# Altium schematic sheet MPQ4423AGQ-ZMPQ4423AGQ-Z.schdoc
size 127 x 101 mm
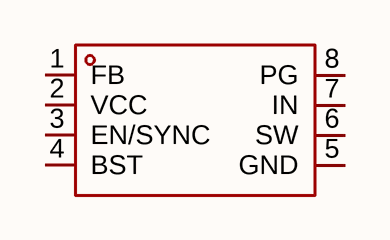
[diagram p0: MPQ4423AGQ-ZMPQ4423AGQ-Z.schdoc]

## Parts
U?  mpq4423agq-z  [QFN-8_L3.0-W3.0-P0.65-TL-MPQ4423HGQ-Z]  (value not drawn)

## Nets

Not connected (* = marked no-connect by the designer): U? 1(FB) 2(VCC) 3(EN/SYNC) 4(BST) 5(GND) 6(SW) 7(IN) 8(PG)

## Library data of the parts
U? = mpq4423agq-z: 功能类型:降压型;工作电压:4V~36V;输出电压:800mV~32.4V;输出电流:3A;输出类型:可调;; Manufacturer: MPS(芯源); AddInBom: yes; Function: 降压型; Voltage - Supply: 4V~36V; Output Current: 3A; Frequency - Switching: 410kHz; Synchronous Rectifier: 是; Number of Outputs: 1; Topology: 降压式; Quiescent Current: 600uA; Switch tube (built-in/external): 内置; Output Type: 可调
